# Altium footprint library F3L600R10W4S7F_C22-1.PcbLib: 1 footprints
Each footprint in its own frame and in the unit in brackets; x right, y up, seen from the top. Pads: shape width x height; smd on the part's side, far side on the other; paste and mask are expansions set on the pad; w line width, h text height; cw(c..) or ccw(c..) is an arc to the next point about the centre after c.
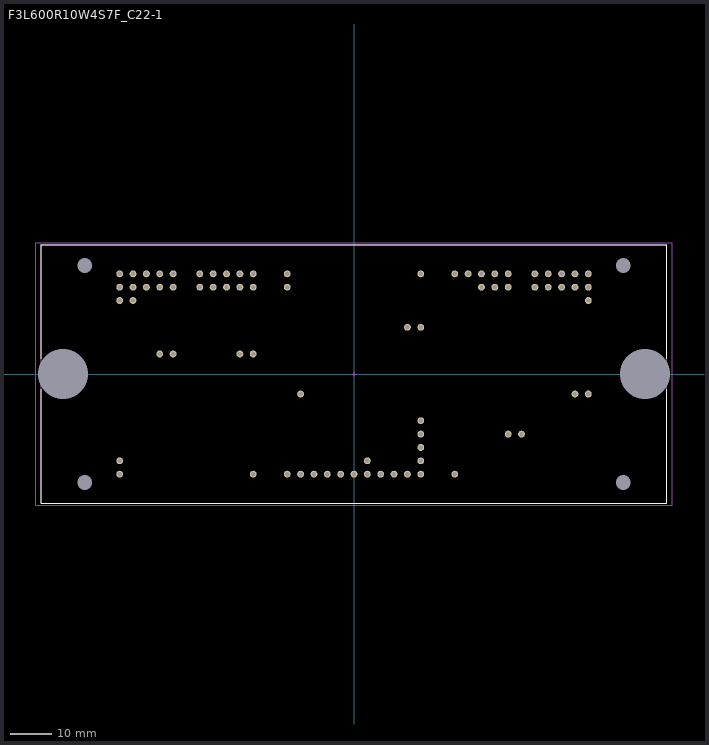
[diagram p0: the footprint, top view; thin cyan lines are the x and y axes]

## F3L600R10W4S7F_C22-1 [mm] "Module, THT, 75 pin, 150.00 mm L X 62.00 mm W X 12.30 mm H body"
height 12.3
pads (81):
  round 1.64 hole 1.04 paste+0 mask+0: AC1(16,-11.2) AC2(16,-14.4) AC3(16,-17.6) AC4(16,-20.8) AC5(16,-24) AC6(12.8,-24) AC7(9.6,-24) AC8(6.4,-24) AC9(0,-24) AC10(-3.2,-24) AC11(-6.4,-24) AC12(-9.6,-24) AC13(-12.8,-24) AC14(-16,-24) G1(-46.55,4.8) G2(3.2,-20.8) G3(-16,20.8) G4(52.95,-4.8) G5(-27.35,4.8) G6(36.95,-14.4) HC2(-12.8,-4.8) HC4_1(16,24) HC4_2(24.15,-24) HC5(-24.15,-24) HE1(-43.35,4.8) HE2(3.2,-24) HE3(-16,24) HE4(56.15,-4.8) HE5(-24.15,4.8) HE6(40.15,-14.4) M1_1(-36.95,24) M1_2(-33.75,24) M1_3(-30.55,24) M1_4(-27.35,24) M1_5(-24.15,24) M1_6(-36.95,20.8) M1_7(-33.75,20.8) M1_8(-30.55,20.8) M1_9(-27.35,20.8) M1_10(-24.15,20.8) M2_1(24.15,24) M2_2(27.35,24) M2_3(30.55,24) M2_4(33.75,24) M2_5(36.95,24) M2_6(30.55,20.8) M2_7(33.75,20.8) M2_8(36.95,20.8) N1(43.35,24) N2(46.55,24) N3(49.75,24) N4(52.95,24) N5(56.15,24) N6(43.35,20.8) N7(46.55,20.8) N8(49.75,20.8) N9(52.95,20.8) N10(56.15,20.8) N11(56.15,17.6) P_1(-56.15,24) P_2(-52.95,24) P_3(-49.75,24) P_4(-46.55,24) P_5(-43.35,24) P_6(-56.15,20.8) P_7(-52.95,20.8) P_8(-49.75,20.8) P_9(-46.55,20.8) P_10(-43.35,20.8) P_11(-56.15,17.6) P_12(-52.95,17.6) X1(-56.15,-24) X2(-56.15,-20.8) X3(12.8,11.2) X4(16,11.2)
  round 0 hole 12 unplated paste+0 mask+0: ""(-69.75,0) ""(69.75,0)
  round 0 hole 3.5 unplated paste+0 mask+0: ""(-64.5,-26) ""(-64.5,26) ""(64.5,-26) ""(64.5,26)
Top Overlay:
  lines w0.2: -75,-3.6 -75,-31 75,-31 75,-3.6 ; -75,3.6 -75,31 75,31 75,3.6
M3 (ASY_Text_Top):
  text ".DESIGNATOR" at -3.643,-0.385 h1.2
M13 (CMP_Body_OTL_Top):
  lines w0.1: -75,-31 -75,31 75,31 75,-31 -75,-31
M15 (CMP_Courtyard_Top):
  lines w0.1: -0.5,0 0.5,0 ; 0,-0.5 0,0.5 ; -76.25,-31.5 76.25,-31.5 76.25,31.5 -76.25,31.5 -76.25,-31.5
3D body "MOD-75_3.20P_150.00x62.00x12.00.STEP": height 12, standoff -4.4, extent -75,-31 75,31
